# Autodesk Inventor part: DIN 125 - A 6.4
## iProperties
Created: 2006-02
Part Number: DIN 125 - A 6.4
Material: Steel, Mild
Description: Washer
Document SubType Name: Modeling
Standard: DIN 125
Designer: Andy Moles
Standards Organization: DIN
Language: en-US
Size Designation: A 6.4
Categories: <MemberInstance><Categories><Category DisplayName="Fasteners" InternalName="e4da775c-781d-43d5-af7c-5136215cf5a6" Mnemonic="FSTN"><Category DisplayName="Washers
Density: 7.86 g/cm^3
Author: Andy Moles
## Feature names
1. Body [Extrusion]
